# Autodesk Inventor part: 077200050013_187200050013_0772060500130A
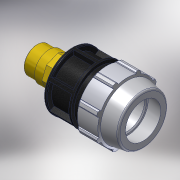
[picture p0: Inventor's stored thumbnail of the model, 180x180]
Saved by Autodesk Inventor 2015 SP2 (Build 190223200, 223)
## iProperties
Created: 2017-02
Part Number: 077200050013_187200050013_0772060500130A
Material: PVC-Piping
Description: PLASSON MALE ADAPTOR INTEGRAL BRASS THREAD 50-1.1/4"
Document SubType Name: Modeling
Designer: KIM
Mass: 92.6774 g
Surface Area: 199.44 cm^2
Volume: 66.1981 cm^3
Density: 1.4 g/cm^3
Appearance: PTFE
Author: KIM
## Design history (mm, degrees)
derived "07720.ipt"
feature "Solid1::07720.ipt"
tag "TaggingFeature1"
body "Solid1"
other parameters: "d4" = 24.57143, "d5" = 24.57143, "d7" = 96, "d8" = 72, "d9" = 24.57143, "d11" = 4.91429, "d12" = 76.8, "d13" = 120 deg, "d14" = 75, "d15" = 10 deg, "d16" = 86.4, "d18" = 2.5, "d19" = 35 deg, "d20" = 17.5 deg, "d21" = 89.28, "d23" = 0, "d25" = 360 deg, "d27" = 1.92, "d34" = 4.8, "d36" = 0, "d42" = 34.4, "d43" = 2.88, "d46" = 1.5, "d49" = 106, "d51" = 172, "d53" = 1, "d55" = 360 deg, "d59" = 34.4, "d60" = 41.91, "d61" = 46.101, "d62" = 22, "d63" = 57.33333, "d64" = 29.337, "d65" = 172, "d66" = 19.7482, "d67" = 0, "d68" = 1, "d71" = 30 deg, "d72" = 37.719, "E_" = 96, "H_" = 172, "l_" = 106, "l_2" = 22, "R_" = 41.91, "d73" = 32.91366
